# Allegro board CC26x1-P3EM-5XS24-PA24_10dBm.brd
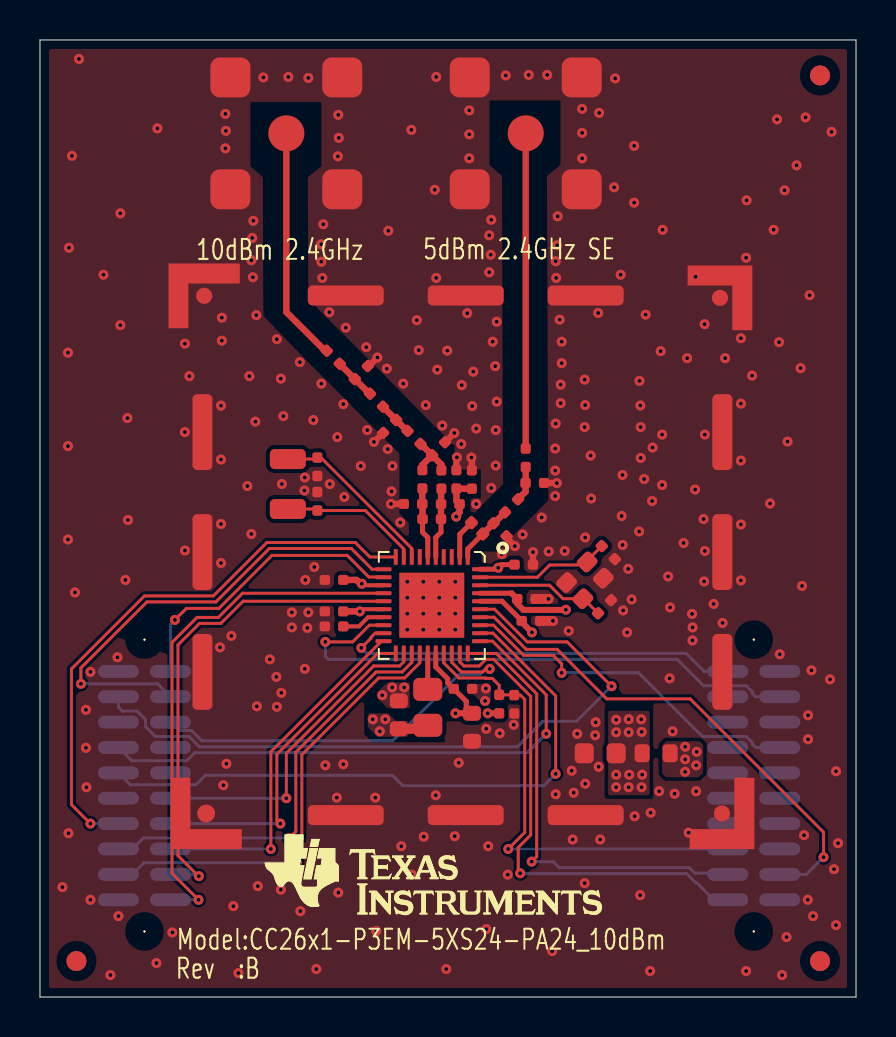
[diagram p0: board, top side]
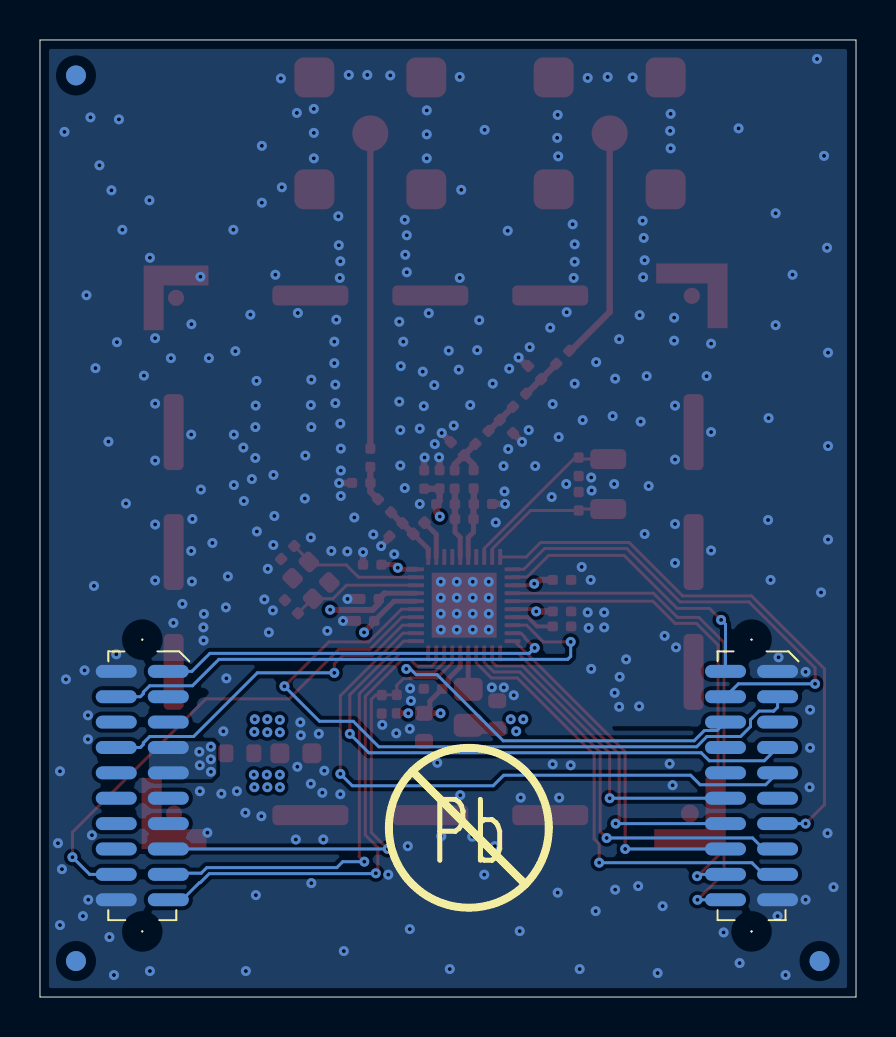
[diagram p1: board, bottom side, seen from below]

Outline 40.83 x 47.9 mm; copper layers: TOP, L2, L3, BOTTOM. Coordinates in mm from the lower left corner of the outline.
Outline path: 0,47.9 0,0 40.83,0 40.83,47.9 0,47.9

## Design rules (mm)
constraint set DEFAULT: min track width 0.15

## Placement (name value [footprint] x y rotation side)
C1  22uF  [CAPC1608X100A2N#2]  28.83 12.2 180 top
C51  12pF  [CAPC1005X60B2N]  20.83 26.37 270 top
C52  10nF  [CAPC1005X60B2N]  21.61 25.44 90 top
C53  1.2pF  [CAPC1005X60B2N]  20.08 25.44 90 top
C54  1.2pF  [CAPC1005X60B2N]  19.62 27.12 45 top
C55  1.4pF  [CAPC1005X60B2N]  17.82 28.88 225 top
C56  1.6pF  [CAPC1005X60B2N]  15.75 30.93 45 top
C57  6.8pF  [CAPC1005X60B2N]  15 31.69 135 top
C61  1.2pF  [CAPC1005X60B2N]  18.2 24.68 0 top
C81  12pF  [CAPC1005X60B2N]  13.88 27 270 top
C91  12pF  [CAPC1005X60B2N]  13.88 24.35 90 top
C131  0.1uF  [CAPC1005X60B2N]  15.17 20.88 180 top
C221  0.1uF  [CAPC1005X60B2N]  15.17 19.3 180 top
C231  1uF  [CAPC1005X60B2N]  15.17 18.55 180 top
C331  22uF  [CAPC1608X100A2N]  17.95 13.42 90 top
C341  22uF  [CAPC1608X100A2N]  21.61 14.2 270 top
C342  0.1uF  [CAPC1005X60B2N]  20.7 15.42 0 top
C351  0.1uF  [CAPC1005X60B2N]  23.73 15.11 270 top
C441  0.1uF  [CAPC1005X60B2N]  24.1 18.83 0 top
C451  0.1uF  [CAPC1005X60B2N]  23.87 19.92 0 top
C461  7.5pF  [CAPC1005X60B2N]  27.92 19.21 45 top
C471  7.5pF  [CAPC1005X60B2N]  28.11 22.57 315 top
C481  0.1uF  [CAPC1005X60B2N]  23.74 21.64 0 top
C482  1.2pF  [CAPC1005X60B2N]  23.34 23.06 135 top
C483  1.2pF  [CAPC1005X60B2N]  25.22 25.73 180 top
C484  12pF  [CAPC1005X60B2N]  24.3 26.52 90 top
FIDU1  FIDU_1MM  [FID100X115B]  1.83 1.8 0 top
FIDU2  FIDU_1MM  [FID100X115B]  39.02 1.8 0 top
FIDU3  FIDU_1MM  [FID100X115B]  39.02 46.12 0 top
FIDU4  FIDU_1MM  [FID100X115B]  1.83 1.8 180 bottom
FIDU5  FIDU_1MM  [FID100X115B]  39.02 1.8 180 bottom
FIDU6  FIDU_1MM  [FID100X115B]  39.02 46.12 180 bottom
FL1  BLM18HE152SN1  [FIL_BLM18HE152SN1DN]  30.12 12.2 0 top
J1  SMA-10V21-TGG  [HUSTSAN_SMA10V21TGGAN]  12.33 43.23 0 top
J2  SMA-10V21-TGG  [HUSTSAN_SMA10V21TGGAN]  24.3 43.23 0 top
L21  15nH  [INDC1005X60C2N]  21.59 23.74 315 top
L51  15nH  [INDC1005X60D2N]  20.06 23.92 180 top
L52  2nH  [INDC1005X60D2N]  20.99 24.67 180 top
L53  1.6nH  [INDC1005X60D2N]  19.04 27.68 135 top
L54  1nH  [INDC1005X60D2N]  17.16 29.54 135 top
L61  2nH  [INDC1005X60D2N]  19.13 25.45 90 top
L331  6.8uH  [INDC2012X150A2N]  19.4 15.4 270 top
L332  2nH  [INDC1005X60D2N]  23.26 24.26 45 top
LBL1  TI_LOGO  [TI_LOGO_1]  12.23 8.13 0 top
LBL2  NON_COMPONENT_LABEL_8mm  [LABEL_PB-FREE_8MM_A2N]  23.58 4.26 180 bottom
NOREF  -  []  0 35.73 0 top
NOREF#2  -  []  38.27 0 90 top
P1  SFM-110-02-S-D-A-K  [SAMTEC_SFM11002AN]  3.92 16.3 0 bottom
P2  SFM-110-02-S-D-A-K  [SAMTEC_SFM11002AN]  34.4 16.3 0 bottom
R351  100k  [RESC1005X40B2N]  22.98 15.12 270 top
SC1  BMI-S-203-F  [MECH_BMIS203_A2N]  8.41 9.09 0 top
SC2  BMIS-203-C  [MECH_BMIS203C]  7.74 8.73 0 top
U1  CC2651P31T0RKPR  [QFNFC40P500X500X100-41A2N]  21.4 22.02 180 top
Y1  32.768kHz  [XTAL_TZ1166C_B2N]  12.4 26.92 270 top
Y2  48MHz  [OSCCC200X160X50-4A2N]  27.37 21.77 225 top

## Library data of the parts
C1 C331 C341 = CAPACITOR: User Part Number: #PN; alternate symbols: (CAPC1608X100A2L,CAPC1608X100A2M)
C51-C57 C61 C81 C91 C131 C221 C231 C342 C351 C441 C451 C461 C471 C481-C484 = CAPACITOR: User Part Number: #PN
FIDU1-FIDU6 = FIDMARK
FL1 = FILTER_2PIN: alternate symbols: (FIL_BLM18HE152SN1DL,FIL_BLM18HE152SN1DM)
J1 J2 = CONN_COAX_1+4: alternate symbols: (HUSTSAN_SMA10V21TGGL,HUSTSAN_SMA10V21TGGM)
L21 L51 L54 = INDUCTOR_HOR_1_2: User Part Number: #PN; alternate symbols: (INDC1005X60C2L,INDC1005X60C2M)
L52 L53 L61 L332 = INDUCTOR_HOR_1_2: User Part Number: #PN
L331 = INDUCTOR: User Part Number: #PN; alternate symbols: (INDC2012X150A2L,INDC2012X150A2M)
LBL1 = TI_LOGO_V1
LBL2 = LABEL_Pb-free_V1: User Part Number: #PN
P1 P2 = CONN_HEADER_2X10_P_S: alternate symbols: (SAMTEC_SFM11002AL,SAMTEC_SFM11002AM)
R351 = RESISTOR: User Part Number: #PN
SC1 = SHIELD_COVER_BMIS-203
SC2 = SHIELD_COVER: User Part Number: #PN
U1 = IC_RF_CC2651P1F32TRKPR_VQFN40: User Part Number: #PN; alternate symbols: (QFNFC40P500X500X100-41A2L,QFNFC40P500X500X100-41A2M)
Y1 = XTAL: User Part Number: #PN; alternate symbols: (XTAL_TZ1166C_B2L,XTAL_TZ1166C_B2M)
Y2 = XTAL_4_V3: User Part Number: #PN; alternate symbols: (OSCCC200X160X50-4A2L,OSCCC200X160X50-4A2M)

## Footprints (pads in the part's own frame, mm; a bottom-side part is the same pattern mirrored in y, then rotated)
CAPC1005X60B2N
  custom 0.125x0.125 smd: 1(0,0) 2(0.924,0)
CAPC1608X100A2N
  custom 0.188x0.188 smd: 1(0,0) 2(1.4,0)
CAPC1608X100A2N#2
  custom 0.237x0.237 smd: 1(0,0) 2(1.6,0)
FID100X115B
  round 1 smd: 1(0,0)
FIL_BLM18HE152SN1DN
  custom 0.188x0.188 smd: 1(0,0) 2(1.4,0)
HUSTSAN_SMA10V21TGGAN
  round 1.801 smd: 1(0,0)
  custom 0.5x0.5 smd: 2(-2.8,-2.8) 3(2.8,-2.8) 4(2.8,2.8) 5(-2.8,2.8)
INDC1005X60C2N
  custom 0.135x0.135 smd: 1(0,0) 2(0.8,0)
INDC1005X60D2N
  custom 0.125x0.125 smd: 1(0,0) 2(0.924,0)
INDC2012X150A2N
  custom 0.287x0.287 smd: 1(0,0) 2(1.8,0)
MECH_BMIS203_A2N
  custom 0.892x0.892 smd: 1(-0.1,0.1)
  custom 0.25x0.25 smd: 2(6.885,0.015) 3(12.885,0.015) 4(18.885,0.015) 6(25.725,7.185) 7(25.725,13.185) 8(25.725,19.185) 10(18.885,26.025) 11(12.885,26.025) 12(6.885,26.025) 14(-0.285,19.185) 15(-0.285,13.185) 16(-0.285,7.185)
  custom 0.81x0.81 smd: 5(25.705,0.1) 9(25.605,25.905) 13(-0.2,26.005)
OSCCC200X160X50-4A2N
  custom 0.2x0.2 smd: 1(0,0) 2(1.45,0) 3(1.45,1.15) 4(0,1.15)
QFNFC40P500X500X100-41A2N
  custom 0.05x0.05 smd: 1(0,0) 2(0.4,0) 3(0.8,0) 4(1.2,0) 5(1.6,0) 6(2,0) 7(2.4,0) 8(2.8,0) 9(3.2,0) 10(3.6,0) 11(4.215,0.615) 12(4.215,1.015) 13(4.215,1.415) 14(4.215,1.815) 15(4.215,2.215) 16(4.215,2.615) 17(4.215,3.015) 18(4.215,3.415) 19(4.215,3.815) 20(4.215,4.215) 21(3.6,4.83) 22(3.2,4.83) 23(2.8,4.83) 24(2.4,4.83) 25(2,4.83) 26(1.6,4.83) 27(1.2,4.83) 28(0.8,4.83) 29(0.4,4.83) 30(0,4.83) 31(-0.615,4.215) 32(-0.615,3.815) 33(-0.615,3.415) 34(-0.615,3.015) 35(-0.615,2.615) 36(-0.615,2.215) 37(-0.615,1.815) 38(-0.615,1.415) 39(-0.615,1.015) 40(-0.615,0.615)
  rect 3.25x3.25 smd: 41(1.8,2.415)
RESC1005X40B2N
  custom 0.125x0.125 smd: 1(0,0) 2(0.924,0)
SAMTEC_SFM11002AN
  round 0.099 hole 1.501 unplated: (1.302,-1.588) (1.302,13.017)
  oval 2.05x0.65 smd: 1(0,0) 2(2.604,0) 3(0,1.27) 4(2.604,1.27) 5(0,2.54) 6(2.604,2.54) 7(0,3.81) 8(2.604,3.81) 9(0,5.08) 10(2.604,5.08) 11(0,6.35) 12(2.604,6.35) 13(0,7.62) 14(2.604,7.62) 15(0,8.89) 16(2.604,8.89) 17(0,10.16) 18(2.604,10.16) 19(0,11.43) 20(2.604,11.43)
XTAL_TZ1166C_B2N
  custom 0.25x0.25 smd: 1(0,0) 2(2.5,0)

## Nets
GND: C1.2 C51.1 C52.2 C54.2 C55.2 C56.2 C61.1 C81.2 C91.2 C131.2 C221.2 C231.2 C331.2 C341.2 C342.2 C351.2 C441.2 C451.2 C461.2 C471.2 C481.2 C482.1 C483.1 J1.2 J1.3 J1.4 J1.5 J2.2 J2.3 J2.4 J2.5 P1.1 P1.19 P2.2 P2.20 SC1.1 SC1.2 SC1.3 SC1.4 SC1.5 SC1.6 SC1.7 SC1.8 SC1.9(GND#9) SC1.10 SC1.11 SC1.12 SC1.13 SC1.14 SC1.15 SC1.16 U1.41 Y2.2 Y2.4(GND#4)
VDD_EB: FL1.2 P2.7 P2.9
VDDR: C51.2 C52.1 C331.1 C451.1 C481.1 L52.1 L331.2 U1.37 U1.40
VDDS: C1.1 C131.1 C221.1 C341.1 C342.1 C441.1 FL1.1 R351.2 U1.13 U1.16 U1.26 U1.36
DCDC_SW: L331.1 U1.25
DIO_5: P1.13 U1.10
DIO_6: P1.4 U1.11
DIO_7: P1.2 U1.12
DIO_8: P1.20 U1.14
DIO_9: P1.18 U1.15(DIO_9)
DIO_10: P1.16 U1.20
DIO_11: P1.14 U1.21
DIO_12: P1.12 U1.22
DIO_13: P1.15 U1.23
DIO_14: P1.17 U1.24
DIO_15: P1.6 U1.28
DIO_16 / JTAG TDO: P2.19 U1.29
DIO_17 / JTAG TDI: P2.17 U1.30
DIO_18: P1.7 U1.31
DIO_19: P1.9 U1.32
DIO_20: P2.8 U1.33
DIO_21: P2.18 U1.34
DIO_22: P1.3 U1.35
JTAG_TCK: P2.1 U1.19
JTAG_TMS: P2.4 U1.18
NRESET: C351.1 P2.15 R351.1 U1.27
RX_TX: U1.7
N485705: C81.1 U1.8 Y1.1
N501936: C471.1 U1.39 Y2.1
N501950: C461.1 U1.38 Y2.3
N510840: C482.2 L21.2 L332.1 U1.1
N517777: C61.2 L51.2 L61.1 U1.6
N517785: C53.1 L51.1 L52.2 U1.5
N517815: C53.2 C54.1 L53.1 L61.2
N517942: C55.1 L53.2 L54.1
N518069: C56.1 C57.1 L54.2
N619141: C231.1 U1.17
N621290: C91.1 U1.9 Y1.2
N2446837: C57.2 J1.1
N2472023: L21.1 U1.2
N2472085: C483.2 C484.1 L332.2
N2472556: C484.2 J2.1

Pads without a net: FIDU1 1; FIDU2 1; FIDU3 1; FIDU4 1; FIDU5 1; FIDU6 1; P1 5 8 10 11; P2 3 5 6 10 11 12 13 14 16; U1 3 4

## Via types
v1: diameter 0.5, hole 0.2, TOP to BOTTOM, 368 vias

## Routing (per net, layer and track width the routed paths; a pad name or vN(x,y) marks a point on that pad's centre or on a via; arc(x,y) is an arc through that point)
GND: length 7.1
  TOP w0.32: v1(17.56,24.68) C61.1 ; v1(16.88,32.01) 16.46,31.58 16.4,31.58 ; v1(21.58,27) 21.61,26.98 C52.2 ; 17.16,28.23 16.72,27.78 v1(16.71,27.78) ; v1(23.76,22.57) 23.34,22.98 C482.1 ; C481.2 v1(24.66,22.27) ; 20.27,27.77 v1(20.73,28.23) ; v1(25.86,25.72) 25.85,25.73 C483.1 ; C51.1 20.83,26.98 v1(20.86,27.01)
  TOP w0.5: C441.2 v1(25.66,18.83) ; C451.2 v1(25.44,19.92)
  vias: v1(1.12,5.5) v1(1.45,37.5) v1(1.4,32.25) v1(1.4,27.58) v1(1.4,22.9) v1(1.42,8.2) v1(1.6,42.1) v1(1.75,20.25) v1(1.95,46.95) v1(2.3,14.38) v1(2.3,12.47) v1(2.33,10.5) v1(2.52,16.27) v1(2.52,4.87) v1(3.17,36.15) v1(3.52,1.1) v1(3.88,17) v1(3.92,4.05) v1(4.02,39.23) v1(4.02,33.62) v1(4.27,20.88) v1(4.38,28.97) v1(4.4,23.88) v1(5.83,1.7) v1(5.88,43.48) v1(6.62,3.23) v1(7.25,32.7) v1(7.25,28.27) v1(7.25,22.35) v1(7.47,31.08) v1(9.05,29.6) v1(9.05,26.9) v1(9.05,23.67) v1(9.05,21.72) v1(9,17.5) v1(9.1,34) v1(9.1,32.85) v1(9.17,10.6) v1(9.27,44.2) v1(9.27,42.48) v1(9.3,43.35) v1(9.33,11.67) v1(9.58,18.08) v1(9.67,4.55) v1(9.92,1.2) v1(10.47,31.08) v1(10.38,25.58) v1(10.62,37.99) v1(10.58,36.87) v1(10.65,36.02) v1(10.58,23.17) v1(10.67,38.85) v1(10.77,28.8) v1(10.83,34.12) v1(10.85,14.55) v1(10.9,5.55) v1(11.17,46.02) v1(11.5,16.9) v1(11.85,32.92) v1(11.83,16.02) v1(11.85,14.52) v1(12.05,30.95) v1(12.05,5.38) v1(12.17,29.08) v1(12.1,25.67) v1(12.08,15.22) v1(12.42,46.05) v1(12.6,19.25) v1(12.6,18.5) v1(13,31.77) v1(13.02,4.3) v1(13.25,26) v1(13.23,25.35) v1(13.27,20.88) v1(13.25,16.42) v1(13.42,46) v1(13.42,19.25) v1(13.38,18.47) v1(13.67,28.88) v1(13.72,21.52) v1(13.83,1.4) v1(14.17,38.67) v1(14.08,37.67) v1(14.08,36.8) v1(14.12,35.99) v1(14.08,30.7) v1(14.27,11.6) v1(14.47,34.27) v1(14.5,25.67) v1(14.85,9.98) v1(14.92,44.15) v1(14.95,43) v1(14.9,42.08) v1(14.88,28.02) v1(14.92,5.22) v1(15.17,29.67) v1(15.17,11.65) v1(15.22,25.02) v1(15.3,33.5) v1(16.05,26.58) v1(16.33,32.52) v1(16.38,28.38) v1(16.77,9.98) v1(16.83,3.3) v1(17.12,15.1) v1(17.35,31.45) v1(17.42,38.35) v1(17.4,27.42) v1(17.63,26.58) v1(17.59,25.3) v1(17.62,15.49) v1(18.02,23.75) v1(18.17,30.7) v1(18.08,7.55) v1(18.22,15.49) v1(18.38,20.79) v1(18.38,19.99) v1(18.38,19.19) v1(18.38,18.39) v1(18.58,43.4) v1(18.6,6.12) v1(18.85,33.88) v1(18.95,32.38) v1(19.17,20.79) v1(19.17,19.99) v1(19.17,19.19) v1(19.17,18.39) v1(19.2,8.02) v1(19.3,29.62) v1(19.75,40.4) v1(19.83,46.05) v1(19.83,35.99) v1(19.8,10.1) v1(19.88,31.4) v1(19.97,20.79) v1(19.97,19.99) v1(19.97,19.19) v1(19.97,18.39) v1(20.12,28.6) v1(20.33,1.4) v1(20.38,32.35) v1(20.77,20.79) v1(20.77,19.99) v1(20.77,19.19) v1(20.77,18.39) v1(20.75,8.05) v1(20.95,11.72) v1(21.1,30.62) v1(21.08,27.67) v1(21.47,44.37) v1(21.47,43.17) v1(21.47,41.98) v1(21.38,34.22) v1(21.62,29.58) v1(21.67,31.3) v1(21.83,28.45) v1(21.83,24.67) v1(22.27,14.82) v1(22.31,15.45) v1(22.33,13.42) v1(22.33,3.4) v1(22.42,7.55) v1(22.48,38.12) v1(22.55,37.15) v1(22.48,36.27) v1(22.58,38.9) v1(22.65,32.8) v1(22.58,25.47) v1(22.77,31.58) v1(22.85,33.8) v1(22.85,29.8) v1(22.8,28.38) v1(22.8,26.6) v1(23,13.2) v1(23.1,22.16) v1(23.3,46.12) v1(23.4,6.12) v1(23.7,13.62) v1(24.15,23.15) v1(24.45,46.15) v1(25.1,24) v1(25.37,46.15) v1(25.45,22.3) v1(25.62,2.3) v1(25.77,27.45) v1(25.77,26.35) v1(25.77,25.08) v1(25.87,37.62) v1(25.8,36.83) v1(25.83,35.99) v1(25.8,28.7) v1(25.8,10.15) v1(25.9,39.08) v1(26,33.9) v1(26.05,30.65) v1(26.05,29.72) v1(26.1,32.8) v1(26.1,31.72) v1(26.25,22.33) v1(26.45,18.33) v1(26.6,11.33) v1(26.65,7.88) v1(26.7,10.22) v1(26.87,13.17) v1(27.12,44.45) v1(27.12,43.25) v1(27.12,41.98) v1(27.25,30.9) v1(27.27,29.62) v1(27.25,28.52) v1(27.27,23) v1(27.27,10.67) v1(27.25,5.7) v1(27.55,27.1) v1(27.58,24.95) v1(27.77,13.1) v1(27.8,13.75) v1(27.92,34.24) v1(27.95,11.52) v1(27.98,44.25) v1(28.02,7.88) v1(28.77,45.98) v1(28.73,40.53) v1(29.05,36.15) v1(29.14,26.13) v1(29.1,24.08) v1(29.15,22.62) v1(29.17,19.35) v1(29.37,18.25) v1(29.43,21.43) v1(29.6,19.9) v1(29.73,42.6) v1(29.73,39.76) v1(29.75,9.05) v1(29.99,30.84) v1(30.04,29.6) v1(30.05,28.52) v1(30.05,26.98) v1(29.98,23.3) v1(30.02,5.1) v1(30.23,25.92) v1(30.3,34.15) v1(30.55,9.22) v1(30.52,1.3) v1(30.65,27.5) v1(30.62,24.83) v1(31.05,32.33) v1(30.98,10.3) v1(31.15,38.4) v1(31.12,28.15) v1(31.12,25.62) v1(31.42,21.05) v1(31.52,19.5) v1(31.5,15.95) v1(31.65,13.3) v1(31.75,10.17) v1(32.2,22.72) v1(32.37,31.97) v1(32.45,8.22) v1(32.62,19.17) v1(32.65,18.5) v1(32.64,17.84) v1(32.77,25.4) v1(32.8,36.05) v1(32.83,10.3) v1(33.25,33.67) v1(33.26,28.15) v1(33.2,23.92) v1(33.26,22.33) v1(33.23,20.8) v1(33.7,19.67) v1(34.15,18.72) v1(34.27,31.97) v1(35.06,32.97) v1(35.06,29.7) v1(35.06,26.85) v1(35.06,23.65) v1(35.06,20.85) v1(35.35,39.87) v1(35.33,37) v1(35.33,1.3) v1(35.62,31.1) v1(36.52,24.7) v1(36.7,38.4) v1(36.87,43.92) v1(36.98,32.77) v1(37.01,17.15) v1(37.12,1.1) v1(37.25,40.37) v1(37.35,3) v1(37.4,27.8) v1(37.85,41.62) v1(38.05,31.47) v1(38.12,20.58) v1(38.23,8.1) v1(38.3,44.02) v1(38.42,14.1) v1(38.42,12.9) v1(38.41,4.87) v1(38.5,35.12) v1(38.59,16.35) v1(38.67,4.05) v1(39.52,15.9) v1(39.6,43.3) v1(39.73,6.4) v1(39.83,11.3) v1(39.83,3.6) v1(39.92,7.7)
VDD_EB:
  vias: v1(32.27,11.27) v1(32.28,12.53) v1(32.28,11.9) v1(32.85,12.27) v1(32.83,11.6)
VDDR: length 10.4
  TOP w0.25: U1.37 23.59,20.21 ; C481.1 23.08,21.64 v1(22.92,21.48) 22.85,21.41 U1.40
  TOP w0.3: 23.59,20.21 C451.1 23.87,19.69 24.19,19.38 26.3,19.38 v1(26.31,19.38)
  TOP w0.32: v1(20.83,24.05) 20.83,24.1 20.99,24.27 L52.1 20.83,24.83 20.83,25.45 20.84,25.44 C52.1
  TOP w0.5: L331.2 19.22,13.42 C331.1
  vias: v1(16.65,13.9) v1(17,13.3) v1(17.27,13.9)
VDDS: length 12.6
  TOP w0.2: U1.13 16.17,20.61 v1(16.1,20.69) ; v1(16,19.3) 16.11,19.41 U1.16
  TOP w0.25: U1.36 23.11,19.81 C441.1 ; C341.1 21.33,14.49 21.33,14.8 C342.1 20.4,15.72 20.4,15.92 19.8,16.52 U1.26
  TOP w0.3: v1(24.61,18.25) 24.1,18.76 C441.1 ; C341.1 v1(20.79,14.2) ; R351.2 v1(22.4,14.2)
  TOP w0.32: C131.1 15.83,20.88 16.02,20.69 v1(16.1,20.69) ; C221.1 v1(16,19.3)
  vias: v1(28.83,13.88) v1(28.83,13.25) v1(28.83,11.13) v1(28.82,10.5) v1(29.45,13.9) v1(29.45,13.25) v1(29.45,10.5) v1(29.48,11.13) v1(30.08,13.9) v1(30.1,13.27) v1(30.13,11.13) v1(30.1,10.5)
DCDC_SW: length 1.8
  TOP w0.25: L331.1 U1.25
DIO_5: length 28.7
  TOP w0.15: v1(2.52,8.68) 1.58,9.63 1.58,16.42 5.23,20.08 8.67,20.08 11.35,22.75 15.77,22.75 16.5,22.02 U1.10
  BOTTOM w0.15: P1.13 v1(2.52,8.68)
DIO_6: length 23.6
  TOP w0.15: v1(2.05,15.68) 2.05,16.47 5.35,19.77 8.8,19.77 11.47,22.45 15.58,22.45 16.61,21.41 U1.11
  BOTTOM w0.15: P1.4 5.88,15.67 v1(2.05,15.67)
DIO_7: length 14.9
  TOP w0.15: v1(6.75,18.88) 7.33,19.45 8.95,19.45 11.6,22.1 15.38,22.1 16.45,21.02 17.17,21.02 U1.12
  BOTTOM w0.15: v1(6.75,18.88) 6.53,18.65 P1.2
DIO_8: length 26.4
  TOP w0.15: v1(7.93,4.87) 6.6,6.19 6.6,17.74 7.86,19 8.92,19 10.14,20.21 U1.14
  BOTTOM w0.15: P1.20 7.78,4.87 7.78,4.87 v1(7.93,4.87)
DIO_9: length 24.7
  TOP w0.15: v1(7.95,6.05) 7.93,6.05 6.9,7.08 6.9,17.62 7.98,18.7 9.05,18.7 10.16,19.81 U1.15
  BOTTOM w0.15: v1(7.95,6.05) 7.86,6.14 P1.18
DIO_10: length 17.8
  TOP w0.15: v1(11.55,7.41) 11.55,12.28 17.08,17.81 U1.20
  BOTTOM w0.15: v1(11.55,7.41) P1.16
DIO_11: length 17.1
  TOP w0.15: U1.21 16.89,17.19 11.85,12.15 11.85,8.86 v1(12.02,8.68)
  BOTTOM w0.15: v1(12.02,8.68) P1.14
DIO_12: length 16.2
  TOP w0.15: v1(12.33,9.95) 12.33,12.2 16.69,16.57 17.99,16.57 18.2,16.78 18.2,17.19
  BOTTOM w0.15: v1(12.33,9.95) P1.12
DIO_13: length 21.3
  TOP w0.15: v1(12.47,7.96) 12.8,8.28 12.8,12.25 16.82,16.27 18.12,16.27 18.6,16.75 U1.23
  BOTTOM w0.15: P1.15 4.62,7.41 5.17,7.96 v1(12.47,7.96)
DIO_14: length 22.9
  TOP w0.15: 19,17.19 19,16.73 18.24,15.97 16.94,15.97 13.1,12.13 13.1,7.91 12.85,7.66 v1(12.85,6.72)
  BOTTOM w0.15: P1.17 4.62,6.14 5.21,6.72 v1(12.85,6.72)
DIO_15: length 20.5
  TOP w0.15: U1.28 20.6,16.75 21.08,16.27 22.14,16.27 22.3,16.42 v1(22.5,16.42)
  BOTTOM w0.15: v1(22.5,16.42) 22.3,16.42 22.01,16.14 20.96,16.14 17.65,12.83 8.1,12.83 7.58,13.34 6.95,13.34 P1.6
DIO_16 / JTAG TDO: length 25
  TOP w0.15: v1(24.02,6.19) 23.92,6.29 23.92,7.48 24.55,8.11 24.55,15.05 22.7,16.89 22.3,16.89 21.98,16.57 21.21,16.57 21,16.78 21,17.19
  BOTTOM w0.15: P2.19 33.7,4.87 32.85,5.72 32.81,5.72 32.36,6.17 24.04,6.17 v1(24.02,6.19)
DIO_17 / JTAG TDI: length 22.9
  TOP w0.15: v1(24.6,6.77) 24.85,7.02 24.85,15.17 22.83,17.19 U1.30
  BOTTOM w0.15: P2.17 33.7,6.14 33.64,6.2 32.76,6.2 32.48,6.47 25.98,6.47 25.67,6.77 v1(24.6,6.77)
DIO_18: length 28.6
  TOP w0.15: U1.31 22.64,17.81 25.33,15.12 v1(25.33,13.17)
  BOTTOM w0.15: v1(25.33,13.17) 24.37,12.22 7.74,12.22 7.34,11.83 4.59,11.83 P1.7
DIO_19: length 31.8
  TOP w0.15: v1(25.8,11.17) 25.8,11.17 25.8,15.08 22.67,18.21 U1.32
  BOTTOM w0.15: v1(25.8,11.17) 25.2,10.58 18.15,10.58 17.62,11.1 8.27,11.1 7.8,10.62 4.52,10.62 P1.9
DIO_20: length 17.8
  TOP w0.15: U1.33 22.69,18.61 24.2,17.1 25.67,17.1 26.1,16.67 v1(26.1,16.22)
  BOTTOM w0.15: v1(26.1,16.22) 29.95,16.22 33.14,13.04 35.33,13.04 35.65,12.72 35.65,12.64 35.8,12.49 P2.8
DIO_21: length 25.4
  TOP w0.15: v1(39.2,7) 39.2,8.25 32.52,14.92 28.35,14.92 25.87,17.4 24.33,17.4 22.71,19.01 U1.34
  BOTTOM w0.15: P2.18 38.34,6.14 v1(39.2,7)
DIO_22: length 35.7
  TOP w0.15: U1.35 22.74,19.41 24.37,17.77 26.37,17.77 v1(28.59,15.55)
  BOTTOM w0.15: P1.3 3.92,14.5 4.12,14.31 4.85,14.31 5.28,13.88 5.28,13.53 5.77,13.04 7.46,13.04 7.97,12.52 23.87,12.52 25.15,13.8 26.84,13.8 v1(28.59,15.55)
JTAG_TCK: length 20.3
  TOP w0.15: U1.19 16.77,18.21 16.56,18 16.56,17.96 v1(16.08,17.47)
  BOTTOM w0.15: P2.1 33.23,16.3 32.33,17.2 16.35,17.2 v1(16.08,17.47)
JTAG_TMS: length 27.6
  TOP w0.15: v1(14.27,17.77) 15.64,17.77 16.48,18.61 U1.18
  BOTTOM w0.15: P2.4 35.8,15.03 35.65,15.18 35.65,15.26 35.33,15.58 33.2,15.58 31.87,16.9 14.43,16.9 14.27,17.05 v1(14.27,17.77)
NRESET: length 24.4
  TOP w0.15: v1(23.42,7.41) 24.25,8.23 24.25,14.9 24.04,15.11 C351.1 23.71,15.12 R351.1 22.98,15.6 22.63,15.94 22.3,15.94 22.28,15.97 20.96,15.97 20.62,16.31 20.61,16.31 20.2,16.73 20.2,17.19
  BOTTOM w0.15: v1(23.42,7.41) P2.15
N485705: length 8.5
  TOP w0.15: U1.8 18.6,22.45 14.05,27 C81.1 13.8,26.92 Y1.1
N501936: length 6.8
  TOP w0.15: C471.1 27.37,21.84 Y2.1 27.22,21.62 25.5,21.62 24.89,21.01 U1.39
N501950: length 6.5
  TOP w0.15: U1.38 25.49,20.61 26.17,19.94 27.19,19.94 C461.1
N510840: length 3
  TOP w0.25: L21.2 22.15,23.18 21.4,22.42 U1.1
  TOP w0.32: L21.2 22.15,23.18 22.69,23.71 22.71,23.71 L332.1
N517777: length 3.5
  TOP w0.25: U1.6 19.4,23 19.14,23.26 L51.2
  TOP w0.32: L51.2 19.14,24.66 C61.2 19.12,25.44 L61.1
N517785: length 3.5
  TOP w0.25: U1.5 19.8,23 20.06,23.26 L51.1
  TOP w0.32: C53.1 20.07,25.42 L52.2 20.06,24.67 L51.1
N517815: length 2.7
  TOP w0.32: C54.1 19.13,26.63 L61.2 ; C54.1 19.05,27.68 L53.1 ; C54.1 20.08,26.65 C53.2
N517942: length 1.7
  TOP w0.32: L53.2 18.37,28.33 C55.1 17.16,29.54 L54.1
N518069: length 2.1
  TOP w0.32: C57.1 15,31.68 C56.1 16.48,30.2 16.51,30.2
N619141: length 2.2
  TOP w0.2: U1.17 16.42,19.01 15.96,18.55 C231.1
N621290: length 7
  TOP w0.15: Y1.2 13.8,24.42 C91.1 16.28,24.35 18.2,22.43 18.2,22.02
N2446837: length 11.8
  TOP w0.32: 14.34,32.35 14.26,32.35 12.33,34.28 J1.1
N2472023: length 2
  TOP w0.25: L21.1 21,23.16 21,22.02
N2472085: length 1.8
  TOP w0.32: C484.1 24.3,25.74 C483.2 24.3,25.29 23.92,24.91
N2472556: length 15.8
  TOP w0.32: C484.2 J2.1

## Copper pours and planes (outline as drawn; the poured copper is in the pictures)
GND on TOP: 18.5,14.45 17.4,14.45 16.88,14.97 16.88,15.25 17.38,15.75 18.5,15.75
GND on TOP: 0.45,47.45 0.45,0.45 40.37,0.45 40.37,47.45 ; 5 cut-outs
GND on TOP: 21.35,15.6 21.35,15.48 22.08,14.75 22.55,14.75 22.55,15.58 22.45,15.67 21.42,15.67
GND on BOTTOM: 0.45,47.45 0.45,0.45 40.37,0.45 40.37,47.45 ; 9 cut-outs
GND on L2: 0.45,47.45 0.45,0.45 40.37,0.45 40.37,47.45 ; 2 cut-outs
GND on L3: 0.45,47.45 0.45,0.45 40.37,0.45 40.37,47.45
VDD_EB on TOP: 31.33,12.8 33,12.8 33.17,12.62 33.17,11.22 32.95,11 31.33,11 31.12,11.2 31.12,12.6
VDD_EB on BOTTOM: 32.17,12.8 35.12,12.8 35.37,12.55 35.37,11.15 35.12,10.9 32.25,10.9 32,11.15 32,12.62
VDDR on TOP: 18.42,13.02 16.88,13.02 16.4,13.5 16.4,14.2 17.42,14.2 17.8,13.83 18.42,13.83
VDDR on L3: 22.92,13 26.02,16.05 26.02,20.77 23.08,20.77 20.2,21.53 20.2,24.97 21.47,24.97 21.47,23.16 24.25,23.17 24.25,21.88 27.75,21.88 27.75,13.83 24.92,11 18.67,11 15.97,13.7 15.97,14.3 16.58,14.9 18.47,13
VDDS on TOP: 28.42,14.33 28.42,10.1 30.5,10.1 30.5,14.33
VDDS on L3: 30.7,14.47 30.7,8.79 16.79,8.77 13.8,11.81 13.8,21.33 16.52,21.33 16.52,17.7 24.1,17.7 24.1,18.62 25.87,18.62 25.87,14.47

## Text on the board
Ref Des/Silkscreen Top: Rev  :B | Model:CC26x1-P3EM-5XS24-PA24_10dBm | 10dBm 2.4GHz | 5dBm 2.4GHz SE
XSECTION_CHART: *  SURFACE - AIR 0 MM | L1: TOP CONDUCTOR - COPPER 0.035 MM | *  DIELECTRIC - FR-4 0.175 MM | L2: L2 PLANE - COPPER 0.018 MM | *  DIELECTRIC - FR-4 1.14 MM | L3: L3 PLANE - COPPER 0.018 MM | L4: BOTTOM CONDUCTOR - COPPER 0.035 MM | DESIGN CROSS SECTION CHART | ___________________________ | TOTAL THICKNESS 1.60MM +/- 0.16MM
User.5: FIGURE | FINISHED_SIZE | 0.2 | 1.501 | DRILL CHART: TOP to BOTTOM | ALL UNITS ARE IN MILLIMETERS | PLATED | NON-PLATED | QTY | 368 | 4
